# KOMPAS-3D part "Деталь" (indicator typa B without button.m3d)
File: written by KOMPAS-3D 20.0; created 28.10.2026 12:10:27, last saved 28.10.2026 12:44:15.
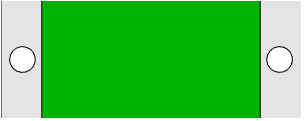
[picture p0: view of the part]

Document properties: Полное имя файла: D:\RicWork\Project-EPS32\box_compas\переключатели и кнопки\indicator typa B without button.m3d

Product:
- Part/product: Деталь
    Масса: 0.00714876

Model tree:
1. Эскиз:1
2. Элемент выдавливания:1
     Расстояние 1 = 1.5
3. Эскиз:2  (with: Элемент выдавливания:1)
4. Элемент выдавливания:2
     Расстояние 2 = 1.5
5. Эскиз:3  (with: Элемент выдавливания:1)
6. Элемент выдавливания:3
     Расстояние 1 = 5.3

Referenced files in D:\RicWork\Project-EPS32\box_compas\переключатели и кнопки\: indicator typa B without button top.png, indicator typa A with button bottom.png
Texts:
  indicator typa B without button top.png
  indicator typa A with button bottom.png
